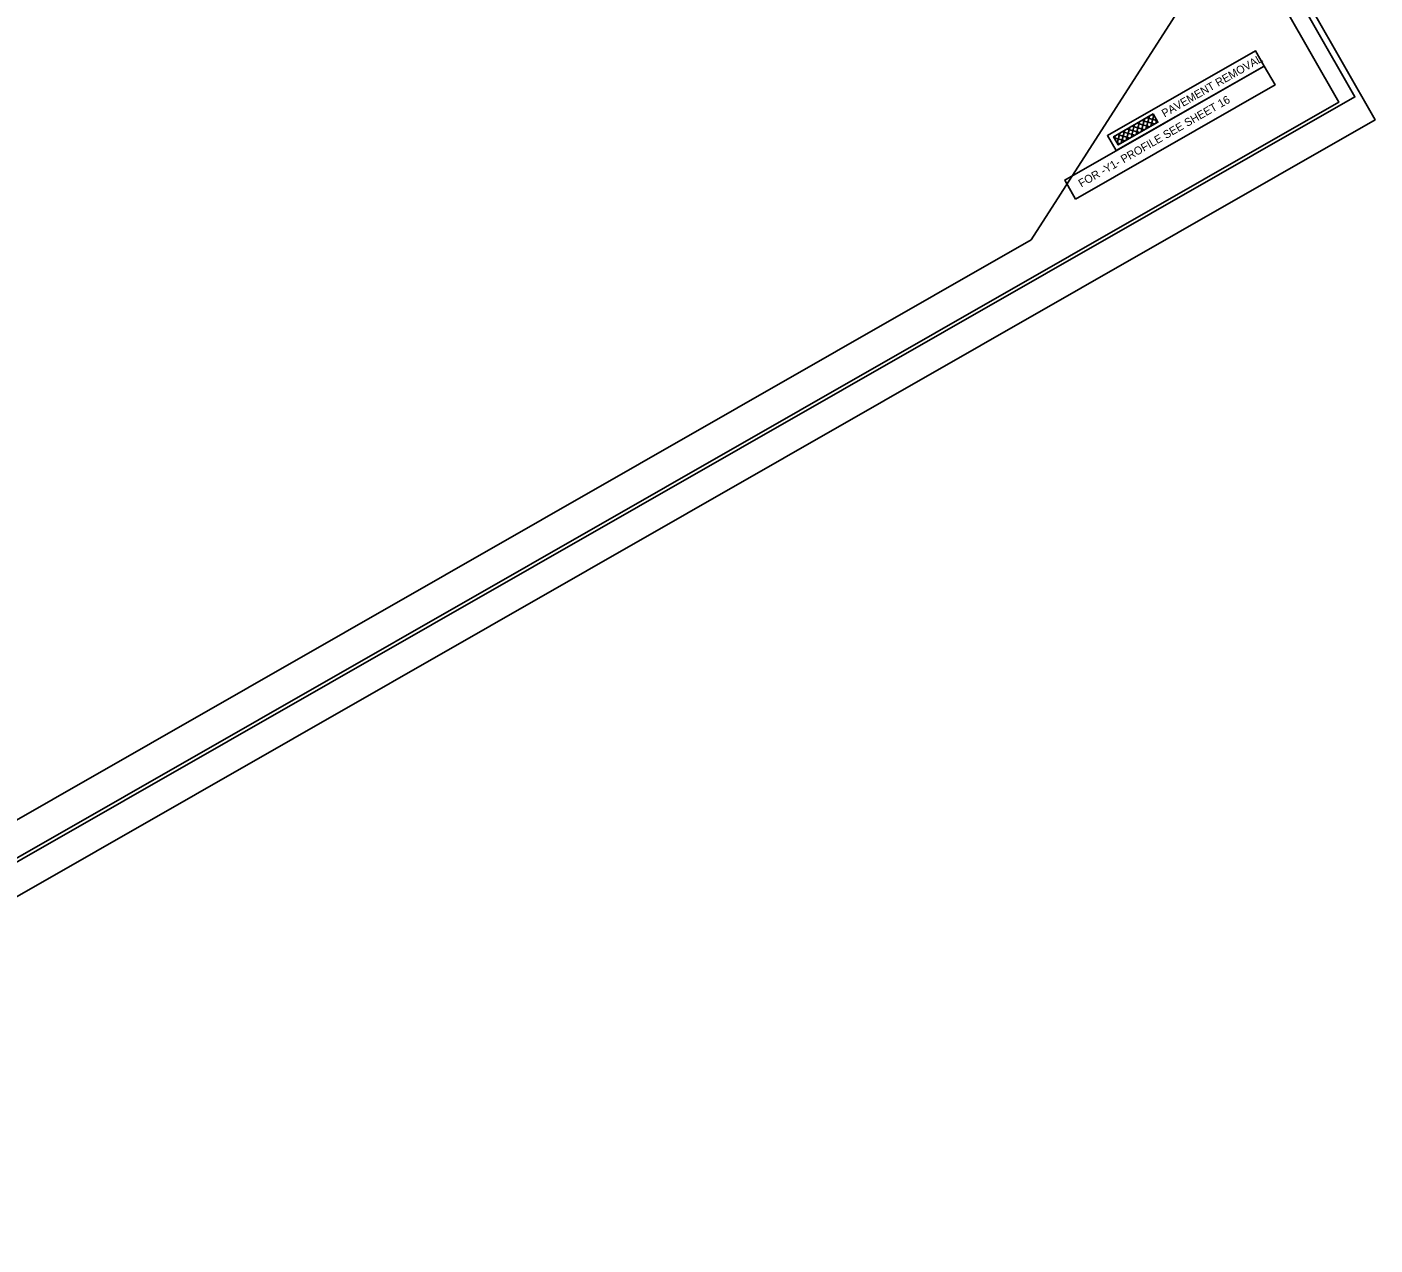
# Model space of a CAD drawing. Extents: x 2344815 to 2346837, y 841953 to 843752.
# Drawn here: x 2345826 to 2346837, y 841953 to 842867 of the extents above; entities that cross this region are included whole.
import ezdxf

# ---------------------------------------------------------------- set-up
doc = ezdxf.new("R2010")
doc.units = 0
for name, color, linetype in [('Default', 7, 'Continuous'), ('Prop DSN Text', 7, 'Continuous'), ('Prop PFL Text', 7, 'Continuous'), ('Sheet Border Standard 30in CELL', 7, 'Continuous'), ('Sheet Clip Boundary CELL', 7, 'Continuous'), ('Sheet Plot Border Inside CELL', 7, 'Continuous'), ('Sheet Plot Border Outside CELL', 7, 'Continuous')]:
    doc.layers.add(name, color=color, linetype=linetype)

msp = doc.modelspace()

# ---------------------------------------------------------------- linework, layer by layer
at = {"layer": 'Default'}
for p, q in [((2346664.9, 842790.3), (2346667.6, 842799.9)), ((2346668.6, 842792.4), (2346670.9, 842800.8)), ((2346669.3, 842800.9), (2346671.1, 842800.4)), ((2346646.5, 842779.8), (2346649.1, 842789.4)), ((2346650.2, 842781.9), (2346652.8, 842791.5)), ((2346650.9, 842790.3), (2346660.5, 842787.7)), ((2346653.9, 842784), (2346656.5, 842793.6)), ((2346654.6, 842792.5), (2346664.2, 842789.8)), ((2346657.6, 842786.1), (2346660.2, 842795.7)), ((2346658.2, 842794.6), (2346667.8, 842791.9)), ((2346661.3, 842788.2), (2346663.9, 842797.8)), ((2346661.9, 842796.7), (2346671.5, 842794.1)), ((2346665.6, 842798.8), (2346673.2, 842796.7)), ((2346672.3, 842794.5), (2346673, 842797.1)), ((2346641.2, 842783.7), (2346649.4, 842781.4)), ((2346641.3, 842783.4), (2346641.8, 842785.1)), ((2346643.3, 842780), (2346645.7, 842779.3)), ((2346643.4, 842779.7), (2346645.5, 842787.3)), ((2346643.5, 842786.1), (2346653.1, 842783.5)), ((2346647.2, 842788.2), (2346656.8, 842785.6))]:
    msp.add_line(p, q, dxfattribs=at)
for points in [[(2346642.6, 842774.1), (2346753.7, 842837.5), (2346747.2, 842848.9), (2346636.1, 842785.4)], [(2346670.5, 842801.6), (2346640.7, 842784.5), (2346644.2, 842778.4), (2346674, 842795.4)]]:
    msp.add_lwpolyline(points, close=True, dxfattribs=at)
at = {"layer": 'Prop PFL Text'}
msp.add_lwpolyline([(2346612.2, 842737.8), (2346761.8, 842823.4), (2346753.7, 842837.5), (2346604.1, 842752)], close=True, dxfattribs=at)
at = {"layer": 'Sheet Border Standard 30in CELL'}
msp.add_lwpolyline([(2346288.2, 843721.9), (2344973.7, 842970.1), (2345494.9, 842058.6), (2346809.5, 842810.4)], close=True, dxfattribs=at)
at = {"layer": 'Sheet Clip Boundary CELL'}
msp.add_lwpolyline([(2345008, 842960.9), (2345464.5, 842162.6), (2345542.9, 842193.6), (2345576.3, 842133.9), (2345624.5, 842161.5), (2346579, 842707.3), (2346706.4, 842906.1), (2346706.4, 842906.1), (2346706.4, 842906.1), (2346027.7, 843544), (2346027.7, 843544), (2346027.7, 843544), (2346023.3, 843541.5)], close=True, dxfattribs=at)
at = {"layer": 'Sheet Plot Border Inside CELL'}
msp.add_lwpolyline([(2346297.9, 843730.3), (2344837.5, 842895.1), (2345361.2, 841979.2), (2346821.7, 842814.4)], close=True, dxfattribs=at)
at = {"layer": 'Sheet Plot Border Outside CELL'}
msp.add_lwpolyline([(2346290.7, 843752.1), (2344815, 842908.1), (2345361, 841953.2), (2346836.8, 842797.2)], close=True, dxfattribs=at)

# ---------------------------------------------------------------- texts
at = {"layer": 'Prop DSN Text'}
for s, p in [('PAVEMENT REMOVAL', (2346678.9, 842798.9)), ('FOR -Y1- PROFILE SEE SHEET 16', (2346616.5, 842746.4))]:
    msp.add_text(s, height=6, rotation=29.7645, dxfattribs=at).set_placement(p)

doc.saveas('drawing.dxf')
